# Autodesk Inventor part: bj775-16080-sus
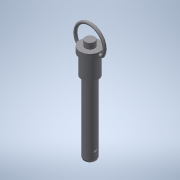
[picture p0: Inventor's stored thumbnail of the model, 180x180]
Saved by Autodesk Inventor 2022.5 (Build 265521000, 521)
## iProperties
Created: 2016-12
Part Number: bj775-16080-sus
Material: 一般
Document SubType Name: Modeling
Designer: imaocorp
Density: 1 g/cm^3
Appearance: 既定
Author: imaocorp
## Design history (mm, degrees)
node "bj775-16080-sus.x_t1"
node "bj775-16080-sus"
node "Base1"
